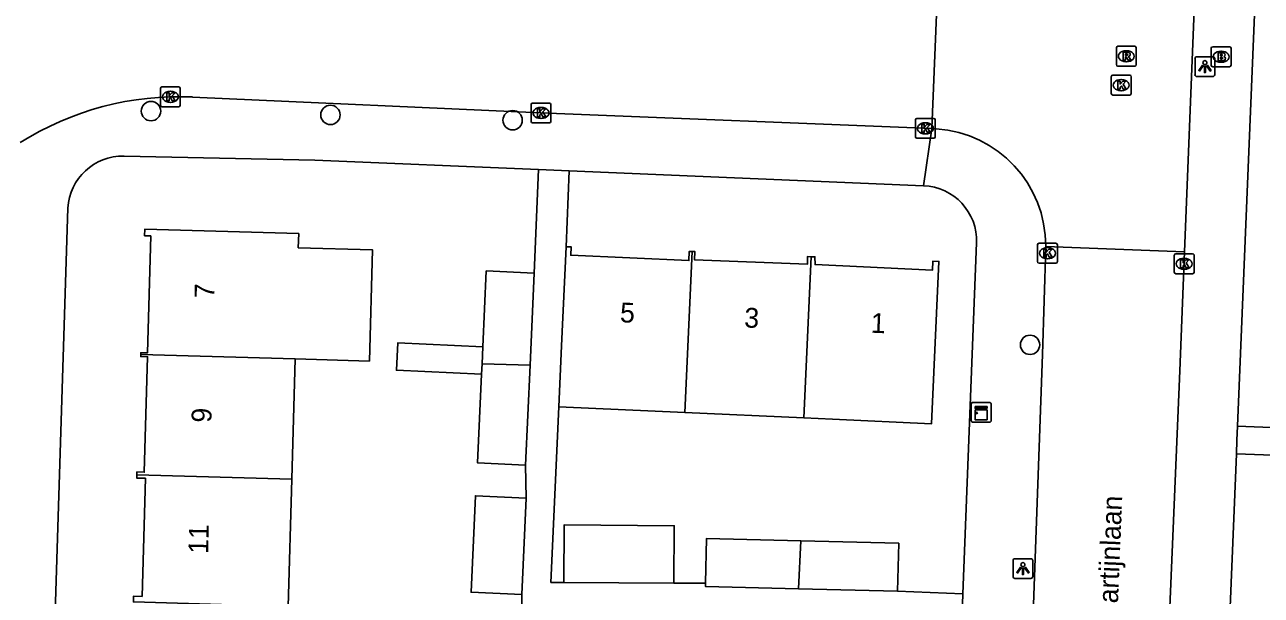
# Model space of a CAD drawing. Extents: x 160077 to 160945, y 386481 to 387498.
# Drawn here: x 160560.3 to 160622.7, y 386684.8 to 386713.6 of the extents above; entities that cross this region are included whole.
import ezdxf

# ---------------------------------------------------------------- set-up
doc = ezdxf.new("R2010")
doc.units = 0
for name, color, linetype in [('IMGEO_Boom', 7, 'Continuous'), ('IMGEO_Brandkraan', 7, 'Continuous'), ('IMGEO_Kast', 7, 'Continuous'), ('IMGEO_Kolk', 7, 'Continuous'), ('IMGEO_Lichtpunt', 7, 'Continuous'), ('IMGEO_Openbare_ruimte_label', 7, 'Continuous'), ('IMGEO_Pand', 7, 'Continuous'), ('IMGEO_Pand_nummerreeks', 7, 'Continuous'), ('IMGEO_Rijbaan_lokaal_open', 7, 'Continuous'), ('IMGEO_Rioolput', 7, 'Continuous'), ('IMGEO_Voetpad_open', 7, 'Continuous')]:
    doc.layers.add(name, color=color, linetype=linetype)

msp = doc.modelspace()

# ---------------------------------------------------------------- linework, layer by layer
at = {"layer": 'IMGEO_Boom'}
for centre in [(160566.638, 386709.27), (160575.691, 386709.078), (160584.883, 386708.809), (160610.987, 386697.475)]:
    msp.add_circle(centre, 0.489, dxfattribs=at)
at = {"layer": 'IMGEO_Brandkraan'}
for p, q in [((160620.126, 386711.585), (160620.126, 386712.437)), ((160620.201, 386712.511), (160621.053, 386712.511)), ((160620.614, 386712.291), (160620.639, 386712.291)), ((160621.127, 386712.437), (160621.127, 386711.585)), ((160620.637, 386711.731), (160620.612, 386711.731)), ((160621.053, 386711.511), (160620.201, 386711.511))]:
    msp.add_line(p, q, dxfattribs=at)
for points in [[(160620.126, 386711.585), (160620.126, 386712.437)], [(160620.201, 386712.511), (160621.053, 386712.511)], [(160620.474, 386712.211), (160620.474, 386711.811), (160620.687, 386711.811)], [(160620.705, 386712.211), (160620.474, 386712.211)], [(160621.127, 386712.437), (160621.127, 386711.585)], [(160620.653, 386712.13), (160620.599, 386712.13), (160620.599, 386712.054)], [(160620.599, 386712.054), (160620.652, 386712.054)], [(160620.661, 386711.978), (160620.599, 386711.978), (160620.599, 386711.897)], [(160620.599, 386711.897), (160620.661, 386711.897)], [(160621.053, 386711.511), (160620.201, 386711.511)]]:
    msp.add_lwpolyline(points, dxfattribs=at)
for centre, radius, start, end in [((160620.203, 386712.435), 0.0765, 91.55205, 178.44795), ((160620.203, 386712.435), 0.0765, 91.55205, 178.44795), ((160620.709, 386712.066), 0.145, 59.4692, 91.53667), ((160620.734, 386712.113), 0.0922, 285.51372, 58.15012), ((160621.051, 386712.435), 0.0765, 1.55205, 88.44795), ((160621.051, 386712.435), 0.0765, 1.55205, 88.44795), ((160620.203, 386711.587), 0.0765, 181.55205, 268.44795), ((160620.203, 386711.587), 0.0765, 181.55205, 268.44795), ((160620.654, 386712.092), 0.0379, 267.82845, 90.93552), ((160620.662, 386711.937), 0.0404, 269.87594, 90.50774), ((160620.693, 386712.062), 0.251, 268.66757, 293.53466), ((160620.739, 386711.921), 0.105, 301.31148, 78.98903), ((160621.051, 386711.587), 0.0765, 271.55205, 358.44795), ((160621.051, 386711.587), 0.0765, 271.55205, 358.44795)]:
    msp.add_arc(centre, radius, start, end, dxfattribs=at)
for centre, major_axis, ratio, start_param, end_param in [((160620.613, 386712.011), (-0.387, 0.002), 0.722429, 4.712389, 7.853982), ((160620.638, 386712.011), (-0.39, 0.002), 0.717154, 1.570796, 4.712389)]:
    msp.add_ellipse(centre, major_axis=major_axis, ratio=ratio, start_param=start_param, end_param=end_param, dxfattribs=at)
at = {"layer": 'IMGEO_Kast'}
for p, q in [((160608.021, 386693.648), (160608.021, 386694.489)), ((160608.021, 386694.489), (160608.021, 386693.648)), ((160608.096, 386694.573), (160608.937, 386694.573)), ((160608.937, 386694.573), (160608.096, 386694.573)), ((160609.021, 386694.498), (160609.021, 386693.657)), ((160609.021, 386693.657), (160609.021, 386694.498)), ((160608.946, 386693.573), (160608.105, 386693.573)), ((160608.105, 386693.573), (160608.946, 386693.573))]:
    msp.add_line(p, q, dxfattribs=at)
for points in [[(160608.216, 386694.363), (160608.816, 386694.363), (160608.816, 386694.278), (160608.216, 386694.278), (160608.216, 386694.363)], [(160608.216, 386694.188), (160608.816, 386694.188), (160608.816, 386693.699), (160608.216, 386693.699), (160608.216, 386694.188)]]:
    msp.add_lwpolyline(points, dxfattribs=at)
msp.add_circle((160608.3, 386694.037), 0.0377, dxfattribs=at)
for centre, start, end in [((160608.099, 386694.495), 92.4484, 184.28452), ((160608.099, 386694.495), 92.4484, 184.28452), ((160608.943, 386694.495), 2.4484, 94.28452), ((160608.943, 386694.495), 2.4484, 94.28452), ((160608.099, 386693.651), 182.4484, 274.28452), ((160608.099, 386693.651), 182.4484, 274.28452), ((160608.943, 386693.651), 272.4484, 4.28452), ((160608.943, 386693.651), 272.4484, 4.28452)]:
    msp.add_arc(centre, 0.0779, start, end, dxfattribs=at)
at = {"layer": 'IMGEO_Kolk'}
for p, q in [((160615.087, 386710.154), (160615.087, 386711.006)), ((160615.162, 386711.08), (160616.014, 386711.08)), ((160616.088, 386711.006), (160616.088, 386710.154)), ((160567.116, 386709.564), (160567.116, 386710.416)), ((160567.191, 386710.49), (160568.043, 386710.49)), ((160568.117, 386710.416), (160568.117, 386709.564)), ((160615.598, 386710.3), (160615.573, 386710.3)), ((160615.575, 386710.86), (160615.6, 386710.86)), ((160567.627, 386709.71), (160567.602, 386709.71)), ((160567.604, 386710.27), (160567.629, 386710.27)), ((160585.888, 386709.677), (160586.74, 386709.677)), ((160616.014, 386710.08), (160615.162, 386710.08)), ((160568.043, 386709.49), (160567.191, 386709.49)), ((160585.813, 386708.751), (160585.813, 386709.603)), ((160586.301, 386709.457), (160586.326, 386709.457)), ((160586.814, 386709.603), (160586.814, 386708.751)), ((160586.74, 386708.677), (160585.888, 386708.677)), ((160586.324, 386708.897), (160586.299, 386708.897)), ((160605.204, 386707.974), (160605.204, 386708.826)), ((160605.279, 386708.9), (160606.131, 386708.9)), ((160605.692, 386708.68), (160605.717, 386708.68)), ((160606.205, 386708.826), (160606.205, 386707.974)), ((160606.131, 386707.9), (160605.279, 386707.9)), ((160605.715, 386708.12), (160605.69, 386708.12)), ((160611.364, 386701.673), (160611.364, 386702.525)), ((160611.439, 386702.599), (160612.291, 386702.599)), ((160611.852, 386702.379), (160611.877, 386702.379)), ((160612.365, 386702.525), (160612.365, 386701.673)), ((160612.291, 386701.599), (160611.439, 386701.599)), ((160611.875, 386701.819), (160611.85, 386701.819)), ((160618.263, 386701.139), (160618.263, 386701.991)), ((160618.338, 386702.065), (160619.19, 386702.065)), ((160618.751, 386701.845), (160618.776, 386701.845)), ((160619.264, 386701.991), (160619.264, 386701.139)), ((160619.19, 386701.065), (160618.338, 386701.065)), ((160618.774, 386701.285), (160618.749, 386701.285))]:
    msp.add_line(p, q, dxfattribs=at)
for points in [[(160615.087, 386710.154), (160615.087, 386711.006)], [(160615.162, 386711.08), (160616.014, 386711.08)], [(160616.088, 386711.006), (160616.088, 386710.154)], [(160567.116, 386709.564), (160567.116, 386710.416)], [(160567.191, 386710.49), (160568.043, 386710.49)], [(160568.117, 386710.416), (160568.117, 386709.564)], [(160615.408, 386710.78), (160615.531, 386710.78), (160615.531, 386710.629), (160615.661, 386710.78), (160615.825, 386710.78), (160615.679, 386710.629), (160615.832, 386710.38), (160615.68, 386710.38), (160615.595, 386710.544), (160615.531, 386710.477), (160615.531, 386710.38), (160615.408, 386710.38), (160615.408, 386710.78)], [(160567.437, 386710.19), (160567.56, 386710.19), (160567.56, 386710.039), (160567.69, 386710.19), (160567.854, 386710.19), (160567.708, 386710.039), (160567.861, 386709.79), (160567.709, 386709.79), (160567.624, 386709.954), (160567.56, 386709.887), (160567.56, 386709.79), (160567.437, 386709.79), (160567.437, 386710.19)], [(160585.888, 386709.677), (160586.74, 386709.677)], [(160616.014, 386710.08), (160615.162, 386710.08)], [(160568.043, 386709.49), (160567.191, 386709.49)], [(160585.813, 386708.751), (160585.813, 386709.603)], [(160586.134, 386709.377), (160586.257, 386709.377), (160586.257, 386709.226), (160586.387, 386709.377), (160586.551, 386709.377), (160586.405, 386709.226), (160586.558, 386708.977), (160586.406, 386708.977), (160586.321, 386709.141), (160586.257, 386709.074), (160586.257, 386708.977), (160586.134, 386708.977), (160586.134, 386709.377)], [(160586.814, 386709.603), (160586.814, 386708.751)], [(160586.74, 386708.677), (160585.888, 386708.677)], [(160605.204, 386707.974), (160605.204, 386708.826)], [(160605.279, 386708.9), (160606.131, 386708.9)], [(160605.525, 386708.6), (160605.648, 386708.6), (160605.648, 386708.449), (160605.778, 386708.6), (160605.942, 386708.6), (160605.796, 386708.449), (160605.949, 386708.2), (160605.797, 386708.2), (160605.712, 386708.364), (160605.648, 386708.297), (160605.648, 386708.2), (160605.525, 386708.2), (160605.525, 386708.6)], [(160606.205, 386708.826), (160606.205, 386707.974)], [(160606.131, 386707.9), (160605.279, 386707.9)], [(160611.364, 386701.673), (160611.364, 386702.525)], [(160611.439, 386702.599), (160612.291, 386702.599)], [(160611.685, 386702.299), (160611.808, 386702.299), (160611.808, 386702.148), (160611.938, 386702.299), (160612.102, 386702.299), (160611.956, 386702.148), (160612.109, 386701.899), (160611.957, 386701.899), (160611.872, 386702.063), (160611.808, 386701.996), (160611.808, 386701.899), (160611.685, 386701.899), (160611.685, 386702.299)], [(160612.365, 386702.525), (160612.365, 386701.673)], [(160612.291, 386701.599), (160611.439, 386701.599)], [(160618.263, 386701.139), (160618.263, 386701.991)], [(160618.338, 386702.065), (160619.19, 386702.065)], [(160618.584, 386701.765), (160618.707, 386701.765), (160618.707, 386701.614), (160618.837, 386701.765), (160619.001, 386701.765), (160618.855, 386701.614), (160619.008, 386701.365), (160618.856, 386701.365), (160618.771, 386701.529), (160618.707, 386701.462), (160618.707, 386701.365), (160618.584, 386701.365), (160618.584, 386701.765)], [(160619.264, 386701.991), (160619.264, 386701.139)], [(160619.19, 386701.065), (160618.338, 386701.065)]]:
    msp.add_lwpolyline(points, dxfattribs=at)
for centre, start, end in [((160615.164, 386711.004), 91.55205, 178.44795), ((160615.164, 386711.004), 91.55205, 178.44795), ((160616.012, 386711.004), 1.55205, 88.44795), ((160616.012, 386711.004), 1.55205, 88.44795), ((160567.193, 386710.414), 91.55205, 178.44795), ((160567.193, 386710.414), 91.55205, 178.44795), ((160568.041, 386710.414), 1.55205, 88.44795), ((160568.041, 386710.414), 1.55205, 88.44795), ((160585.89, 386709.601), 91.55205, 178.44795), ((160585.89, 386709.601), 91.55205, 178.44795), ((160586.738, 386709.601), 1.55205, 88.44795), ((160586.738, 386709.601), 1.55205, 88.44795), ((160615.164, 386710.156), 181.55205, 268.44795), ((160615.164, 386710.156), 181.55205, 268.44795), ((160616.012, 386710.156), 271.55205, 358.44795), ((160616.012, 386710.156), 271.55205, 358.44795), ((160567.193, 386709.566), 181.55205, 268.44795), ((160567.193, 386709.566), 181.55205, 268.44795), ((160568.041, 386709.566), 271.55205, 358.44795), ((160568.041, 386709.566), 271.55205, 358.44795), ((160585.89, 386708.753), 181.55205, 268.44795), ((160585.89, 386708.753), 181.55205, 268.44795), ((160586.738, 386708.753), 271.55205, 358.44795), ((160586.738, 386708.753), 271.55205, 358.44795), ((160605.281, 386708.824), 91.55205, 178.44795), ((160605.281, 386708.824), 91.55205, 178.44795), ((160606.129, 386708.824), 1.55205, 88.44795), ((160606.129, 386708.824), 1.55205, 88.44795), ((160605.281, 386707.976), 181.55205, 268.44795), ((160605.281, 386707.976), 181.55205, 268.44795), ((160606.129, 386707.976), 271.55205, 358.44795), ((160606.129, 386707.976), 271.55205, 358.44795), ((160611.441, 386702.523), 91.55205, 178.44795), ((160611.441, 386702.523), 91.55205, 178.44795), ((160612.289, 386702.523), 1.55205, 88.44795), ((160612.289, 386702.523), 1.55205, 88.44795), ((160611.441, 386701.675), 181.55205, 268.44795), ((160611.441, 386701.675), 181.55205, 268.44795), ((160612.289, 386701.675), 271.55205, 358.44795), ((160612.289, 386701.675), 271.55205, 358.44795), ((160618.34, 386701.989), 91.55205, 178.44795), ((160618.34, 386701.989), 91.55205, 178.44795), ((160619.188, 386701.989), 1.55205, 88.44795), ((160619.188, 386701.989), 1.55205, 88.44795), ((160618.34, 386701.141), 181.55205, 268.44795), ((160618.34, 386701.141), 181.55205, 268.44795), ((160619.188, 386701.141), 271.55205, 358.44795), ((160619.188, 386701.141), 271.55205, 358.44795)]:
    msp.add_arc(centre, 0.0765, start, end, dxfattribs=at)
for centre, major_axis, ratio, start_param, end_param in [((160615.574, 386710.58), (-0.387, 0.002), 0.722429, 4.712389, 7.853982), ((160615.599, 386710.58), (-0.39, 0.002), 0.717154, 1.570796, 4.712389), ((160567.603, 386709.99), (-0.387, 0.002), 0.722429, 4.712389, 7.853982), ((160567.628, 386709.99), (-0.39, 0.002), 0.717154, 1.570796, 4.712389), ((160586.3, 386709.177), (-0.387, 0.002), 0.722429, 4.712389, 7.853982), ((160586.325, 386709.177), (-0.39, 0.002), 0.717154, 1.570796, 4.712389), ((160605.691, 386708.4), (-0.387, 0.002), 0.722429, 4.712389, 7.853982), ((160605.716, 386708.4), (-0.39, 0.002), 0.717154, 1.570796, 4.712389), ((160611.851, 386702.099), (-0.387, 0.002), 0.722429, 4.712389, 7.853982), ((160611.876, 386702.099), (-0.39, 0.002), 0.717154, 1.570796, 4.712389), ((160618.75, 386701.565), (-0.387, 0.002), 0.722429, 4.712389, 7.853982), ((160618.775, 386701.565), (-0.39, 0.002), 0.717154, 1.570796, 4.712389)]:
    msp.add_ellipse(centre, major_axis=major_axis, ratio=ratio, start_param=start_param, end_param=end_param, dxfattribs=at)
at = {"layer": 'IMGEO_Lichtpunt'}
for p, q in [((160619.309, 386711.918), (160619.309, 386711.111)), ((160619.309, 386711.918), (160619.309, 386711.111)), ((160620.211, 386712.013), (160619.403, 386712.013)), ((160620.211, 386712.013), (160619.403, 386712.013)), ((160620.305, 386711.111), (160620.305, 386711.918)), ((160620.305, 386711.111), (160620.305, 386711.918)), ((160619.403, 386711.017), (160620.211, 386711.017)), ((160619.403, 386711.017), (160620.211, 386711.017)), ((160610.129, 386686.587), (160610.129, 386685.78)), ((160610.129, 386686.587), (160610.129, 386685.78)), ((160611.031, 386686.682), (160610.223, 386686.682)), ((160611.031, 386686.682), (160610.223, 386686.682)), ((160611.125, 386685.78), (160611.125, 386686.587)), ((160611.125, 386685.78), (160611.125, 386686.587)), ((160610.223, 386685.686), (160611.031, 386685.686)), ((160610.223, 386685.686), (160611.031, 386685.686))]:
    msp.add_line(p, q, dxfattribs=at)
for points in [[(160619.683, 386711.582), (160619.722, 386711.554), (160619.534, 386711.292), (160619.496, 386711.319), (160619.683, 386711.582)], [(160619.785, 386711.534), (160619.832, 386711.534), (160619.832, 386711.212), (160619.785, 386711.212), (160619.785, 386711.534)], [(160619.895, 386711.554), (160619.933, 386711.581), (160620.12, 386711.319), (160620.081, 386711.291), (160619.895, 386711.554)], [(160610.503, 386686.251), (160610.542, 386686.223), (160610.354, 386685.961), (160610.316, 386685.988), (160610.503, 386686.251)], [(160610.605, 386686.203), (160610.652, 386686.203), (160610.652, 386685.881), (160610.605, 386685.881), (160610.605, 386686.203)], [(160610.715, 386686.223), (160610.753, 386686.25), (160610.94, 386685.988), (160610.901, 386685.96), (160610.715, 386686.223)]]:
    msp.add_lwpolyline(points, dxfattribs=at)
for centre in [(160619.808, 386711.716), (160610.628, 386686.385)]:
    msp.add_circle(centre, 0.0994, dxfattribs=at)
for centre, start, end in [((160619.403, 386711.918), 90, 180), ((160619.403, 386711.918), 90, 180), ((160620.211, 386711.918), 0, 90), ((160620.211, 386711.918), 0, 90), ((160619.403, 386711.111), 180, 270), ((160619.403, 386711.111), 180, 270), ((160620.211, 386711.111), 270, 0), ((160620.211, 386711.111), 270, 360), ((160610.223, 386686.587), 90, 180), ((160610.223, 386686.587), 90, 180), ((160611.031, 386686.587), 0, 90), ((160611.031, 386686.587), 0, 90), ((160610.223, 386685.78), 180, 270), ((160610.223, 386685.78), 180, 270), ((160611.031, 386685.78), 270, 0), ((160611.031, 386685.78), 270, 360)]:
    msp.add_arc(centre, 0.0946, start, end, dxfattribs=at)
at = {"layer": 'IMGEO_Pand'}
for points in [[(160566.121, 386696.98), (160566.124, 386697.077), (160566.46, 386697.067), (160566.628, 386702.969), (160566.315, 386702.978), (160566.324, 386703.311), (160574.09, 386703.09), (160574.07, 386702.373), (160577.816, 386702.266), (160577.656, 386696.656), (160573.91, 386696.762)], [(160587.216, 386694.348), (160587.356, 386697.43), (160587.582, 386702.424)], [(160587.582, 386702.424), (160587.836, 386702.413), (160587.817, 386701.999), (160593.775, 386701.73), (160593.796, 386702.193), (160593.938, 386702.187)], [(160593.938, 386702.187), (160593.564, 386694.061)], [(160593.938, 386702.187), (160594.081, 386702.18), (160594.062, 386701.762), (160599.756, 386701.544), (160599.753, 386701.931), (160599.942, 386701.924)], [(160599.942, 386701.924), (160600.132, 386701.916), (160600.142, 386701.524), (160606.066, 386701.244), (160606.087, 386701.698), (160606.387, 386701.684), (160606.017, 386693.497), (160601.023, 386693.723), (160599.568, 386693.789)], [(160599.568, 386693.789), (160599.942, 386701.924)], [(160585.97, 386701.098), (160583.55, 386701.207), (160583.377, 386697.374)], [(160585.97, 386701.098), (160585.761, 386696.448)], [(160583.377, 386697.374), (160579.084, 386697.568), (160579.022, 386696.19), (160583.314, 386695.996)], [(160583.338, 386696.516), (160583.377, 386697.374)], [(160565.924, 386690.908), (160565.928, 386691.059), (160566.299, 386691.049), (160566.465, 386696.876), (160566.118, 386696.886), (160566.121, 386696.98)], [(160566.121, 386696.98), (160573.91, 386696.762)], [(160573.91, 386696.762), (160573.737, 386690.689)], [(160583.314, 386695.996), (160583.112, 386691.517), (160585.534, 386691.408)], [(160583.314, 386695.996), (160583.338, 386696.516)], [(160585.761, 386696.448), (160583.338, 386696.516)], [(160585.761, 386696.448), (160585.534, 386691.408)], [(160593.564, 386694.061), (160587.216, 386694.348)], [(160599.568, 386693.789), (160593.564, 386694.061)], [(160565.924, 386690.908), (160565.919, 386690.755), (160566.359, 386690.743), (160566.189, 386684.781), (160565.762, 386684.793), (160565.753, 386684.501), (160570.751, 386684.359), (160573.554, 386684.279), (160573.737, 386690.689)], [(160573.737, 386690.689), (160565.924, 386690.908)], [(160585.563, 386689.746), (160583.006, 386689.861), (160582.786, 386684.988), (160585.343, 386684.872)], [(160585.563, 386689.746), (160585.343, 386684.872)], [(160587.459, 386685.484), (160587.481, 386688.388), (160593.033, 386688.346), (160593.011, 386685.442)], [(160594.611, 386685.442), (160594.669, 386687.706), (160599.422, 386687.585)], [(160599.31, 386685.168), (160599.422, 386687.585)], [(160599.422, 386687.585), (160604.365, 386687.46), (160604.303, 386685.041)], [(160593.011, 386685.442), (160587.459, 386685.484)], [(160599.31, 386685.168), (160594.607, 386685.288), (160594.611, 386685.442)], [(160604.303, 386685.041), (160599.31, 386685.168)]]:
    msp.add_lwpolyline(points, dxfattribs=at)
at = {"layer": 'IMGEO_Rijbaan_lokaal_open'}
for points in [[(160619.524, 386720.686), (160618.787, 386702.164)], [(160606.312, 386715.396), (160606.031, 386708.388)], [(160606.031, 386708.388), (160586.668, 386709.162), (160568.739, 386709.981)], [(160606.255, 386708.379), (160606.031, 386708.388)], [(160609.383, 386642.765), (160610.716, 386672.205), (160611.622, 386696.983), (160611.777, 386702.444)], [(160618.787, 386702.164), (160611.777, 386702.444)], [(160615.656, 386623.956), (160616.069, 386637.291), (160617.271, 386665.941), (160618.548, 386696.166), (160618.787, 386702.164)]]:
    msp.add_lwpolyline(points, dxfattribs=at)
for centre, radius, start, end in [((160568.051, 386694.984), 15.013, 87.37219, 122.24782), ((160605.867, 386702.482), 5.91, 359.63605, 86.23496)]:
    msp.add_arc(centre, radius, start, end, dxfattribs=at)
at = {"layer": 'IMGEO_Rioolput'}
for p, q in [((160615.341, 386711.613), (160615.341, 386712.465)), ((160615.416, 386712.539), (160616.268, 386712.539)), ((160615.829, 386712.319), (160615.854, 386712.319)), ((160616.342, 386712.465), (160616.342, 386711.613)), ((160616.268, 386711.539), (160615.416, 386711.539)), ((160615.852, 386711.759), (160615.827, 386711.759))]:
    msp.add_line(p, q, dxfattribs=at)
for points in [[(160615.341, 386711.613), (160615.341, 386712.465)], [(160615.416, 386712.539), (160616.268, 386712.539)], [(160615.93, 386712.237), (160615.678, 386712.239), (160615.678, 386711.839)], [(160615.856, 386712.158), (160615.802, 386712.158), (160615.802, 386712.077)], [(160616.342, 386712.465), (160616.342, 386711.613)], [(160616.268, 386711.539), (160615.416, 386711.539)], [(160615.678, 386711.839), (160615.802, 386711.839), (160615.802, 386712.001), (160615.813, 386712.001)], [(160615.802, 386712.077), (160615.854, 386712.077)], [(160615.86, 386711.972), (160615.931, 386711.839), (160616.071, 386711.839), (160616.006, 386711.965)]]:
    msp.add_lwpolyline(points, dxfattribs=at)
for centre, radius, start, end in [((160615.418, 386712.463), 0.0765, 91.55205, 178.44795), ((160615.418, 386712.463), 0.0765, 91.55205, 178.44795), ((160615.862, 386712.062), 0.0964, 77.00612, 93.18647), ((160615.929, 386712.127), 0.109, 350.36119, 89.41601), ((160616.266, 386712.463), 0.0765, 1.55205, 88.44795), ((160616.266, 386712.463), 0.0765, 1.55205, 88.44795), ((160615.418, 386711.615), 0.0765, 181.55205, 268.44795), ((160615.418, 386711.615), 0.0765, 181.55205, 268.44795), ((160615.812, 386711.948), 0.0533, 26.02933, 88.69889), ((160615.838, 386712.266), 0.19, 274.7715, 282.96867), ((160615.876, 386712.119), 0.0378, 276.66336, 79.67722), ((160615.927, 386712.127), 0.112, 277.58423, 350.98172), ((160615.911, 386711.912), 0.108, 29.51342, 73.79051), ((160616.266, 386711.615), 0.0765, 271.55205, 358.44795), ((160616.266, 386711.615), 0.0765, 271.55205, 358.44795)]:
    msp.add_arc(centre, radius, start, end, dxfattribs=at)
for centre, major_axis, ratio, start_param, end_param in [((160615.828, 386712.039), (-0.387, 0.002), 0.722429, 4.712389, 7.853982), ((160615.853, 386712.039), (-0.39, 0.002), 0.717154, 1.570796, 4.712389)]:
    msp.add_ellipse(centre, major_axis=major_axis, ratio=ratio, start_param=start_param, end_param=end_param, dxfattribs=at)
at = {"layer": 'IMGEO_Voetpad_open'}
for points in [[(160621.452, 386693.374), (160623.787, 386750), (160624.002, 386755.214)], [(160606.031, 386708.388), (160605.613, 386705.506)], [(160565.277, 386707), (160574.9, 386706.795), (160586.189, 386706.321)], [(160586.189, 386706.321), (160585.97, 386701.098)], [(160587.743, 386706.256), (160586.189, 386706.321)], [(160587.582, 386702.424), (160587.743, 386706.256)], [(160587.743, 386706.256), (160605.613, 386705.506)], [(160561.757, 386682.36), (160562.444, 386704.374)], [(160608.288, 386702.62), (160607.6, 386684.913)], [(160587.459, 386685.484), (160586.815, 386685.489), (160587.216, 386694.348)], [(160621.452, 386693.374), (160621.423, 386692.671), (160621.394, 386691.978)], [(160627.397, 386693.129), (160621.452, 386693.374)], [(160621.394, 386691.978), (160618.61, 386624.44)], [(160621.394, 386691.978), (160627.318, 386691.759)], [(160585.534, 386691.408), (160585.563, 386689.746)], [(160594.611, 386685.442), (160593.011, 386685.442)], [(160585.343, 386684.872), (160585.352, 386683.684), (160575.615, 386681.927), (160561.757, 386682.36)], [(160607.6, 386684.913), (160604.303, 386685.041)], [(160607.539, 386683.345), (160607.6, 386684.913)]]:
    msp.add_lwpolyline(points, dxfattribs=at)
for centre, radius, start, end in [((160565.217, 386704.223), 2.777, 88.76724, 176.88964), ((160605.504, 386702.722), 2.786, 357.90538, 87.74878)]:
    msp.add_arc(centre, radius, start, end, dxfattribs=at)

# ---------------------------------------------------------------- texts
at = {"layer": 'IMGEO_Openbare_ruimte_label'}
msp.add_text('Martijnlaan', height=1, rotation=87.7071, dxfattribs=at).set_placement((160615.378, 386683.308))
at = {"layer": 'IMGEO_Pand_nummerreeks'}
for s, rotation, p in [('7', 88.60792, (160569.833, 386699.812)), ('5', 357.6226, (160590.287, 386698.615)), ('3', 357.6226, (160596.555, 386698.355)), ('1', 357.6226, (160602.935, 386698.089)), ('9', 88.60792, (160569.681, 386693.541)), ('11', 88.60905, (160569.52, 386686.923))]:
    msp.add_text(s, height=1, rotation=rotation, dxfattribs=at).set_placement(p)

doc.saveas('drawing.dxf')
